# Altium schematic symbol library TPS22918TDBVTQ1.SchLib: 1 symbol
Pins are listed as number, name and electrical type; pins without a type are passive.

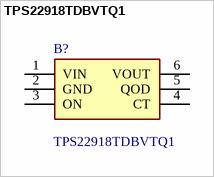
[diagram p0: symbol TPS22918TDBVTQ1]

## TPS22918TDBVTQ1
designator B?
5.5V, 2A, 52m Automotive High-Side Load Switch with Adjustable Rise Time & Quick Output Discharge; Manufacturer_Name: Texas Instruments; Geometry.Height: 1.45mm
footprint SOT95P280X145-6N
pins: 1 VIN, 2 GND, 3 ON, 4 CT, 5 QOD, 6 VOUT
